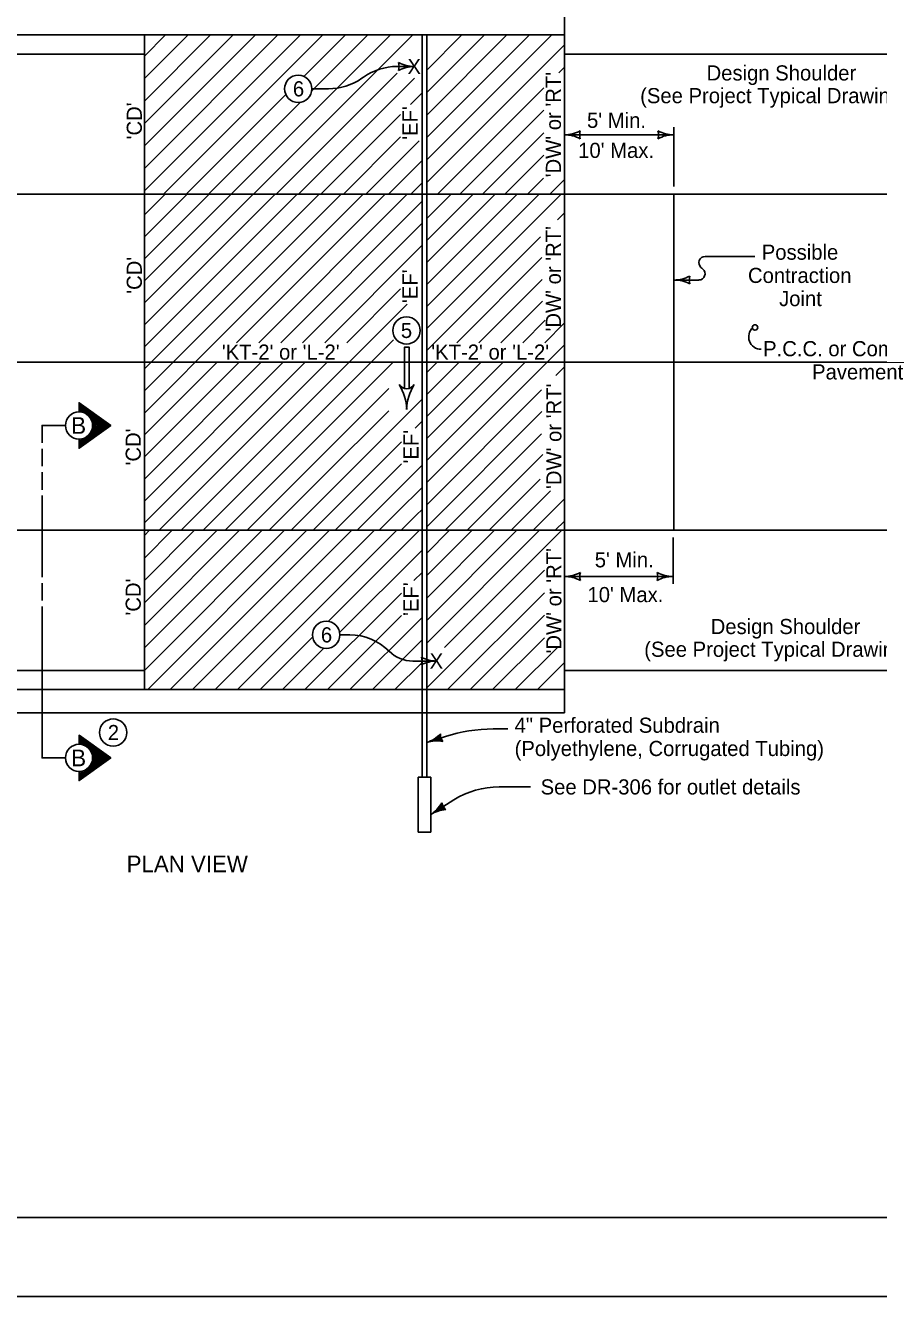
# Model space of a CAD drawing. Extents: x -2135039 to -2131695, y -2139150 to -2136566.
# Drawn here: x -2133962 to -2132834, y -2139150 to -2137471 of the extents above; entities that cross this region are included whole.
import ezdxf

# ---------------------------------------------------------------- set-up
doc = ezdxf.new("R2010")
doc.units = 0
for name, color, linetype in [('Default', 7, 'Continuous'), ('dsnDOTLogo', 7, 'Continuous'), ('Level 1', 7, 'Continuous'), ('Level 2', 7, 'Continuous'), ('Level 3', 7, 'Continuous')]:
    doc.layers.add(name, color=color, linetype=linetype)

msp = doc.modelspace()

# ---------------------------------------------------------------- linework, layer by layer
at = {"layer": 'Default'}
msp.add_line((-2134174.5, -2137483.5), (-2133249.3, -2137483.5), dxfattribs=at)
at = {"layer": 'dsnDOTLogo'}
msp.add_lwpolyline([(-2135038.9, -2139150.4), (-2131694.9, -2139150.4), (-2131694.9, -2136566.4), (-2135038.9, -2136566.4)], close=True, dxfattribs=at)
at = {"layer": 'Level 1'}
msp.add_lwpolyline([(-2134934.4, -2137035.9), (-2131799.4, -2137035.9), (-2131799.4, -2139045.9), (-2134934.4, -2139045.9)], close=True, dxfattribs=at)
at = {"layer": 'Level 2'}
for p, q in [((-2133249.3, -2137452.7), (-2133249.3, -2137509)), ((-2134174.5, -2137483.5), (-2133804.4, -2137483.5)), ((-2133804.4, -2137483.5), (-2134174.5, -2137483.5)), ((-2133804.4, -2137483.5), (-2133804.4, -2138138.1)), ((-2133804.4, -2137689.7), (-2133598.2, -2137483.5)), ((-2133804.4, -2137660), (-2133627.9, -2137483.5)), ((-2133804.4, -2137630.3), (-2133657.6, -2137483.5)), ((-2133804.4, -2137600.6), (-2133687.3, -2137483.5)), ((-2133804.4, -2137570.9), (-2133717, -2137483.5)), ((-2133804.4, -2137541.2), (-2133746.7, -2137483.5)), ((-2133804.4, -2137511.5), (-2133776.4, -2137483.5)), ((-2133779, -2137694), (-2133568.5, -2137483.5)), ((-2133689.9, -2137694), (-2133479.4, -2137483.5)), ((-2133660.2, -2137694), (-2133449.7, -2137483.5)), ((-2133593.7, -2137538.4), (-2133538.8, -2137483.5)), ((-2133583.4, -2137557.8), (-2133509.1, -2137483.5)), ((-2133437.4, -2137694), (-2133437.4, -2137483.5)), ((-2133431.3, -2137483.5), (-2133431.3, -2137694)), ((-2133431.3, -2137648.8), (-2133266, -2137483.5)), ((-2133431.3, -2137619.1), (-2133295.7, -2137483.5)), ((-2133431.3, -2137589.4), (-2133325.4, -2137483.5)), ((-2133431.3, -2137559.7), (-2133355.1, -2137483.5)), ((-2133431.3, -2137530), (-2133384.8, -2137483.5)), ((-2133249.3, -2137694), (-2133249.3, -2137483.5)), ((-2133804.4, -2137509), (-2134174.4, -2137509)), ((-2133804.4, -2137694), (-2133804.4, -2137509)), ((-2133804.4, -2137694), (-2133804.4, -2137509)), ((-2133437.4, -2137694), (-2133437.4, -2137509)), ((-2133431.3, -2137678.5), (-2133249.3, -2137496.6)), ((-2133431.3, -2137694), (-2133431.3, -2137509)), ((-2133249.3, -2137509), (-2132738.5, -2137509)), ((-2133249.3, -2137694), (-2133249.3, -2137509)), ((-2133447.7, -2137525.3), (-2133470.5, -2137525.3)), ((-2133256.6, -2137533.6), (-2133249.3, -2137526.3)), ((-2133630.5, -2137694), (-2133470.6, -2137534.1)), ((-2133600.8, -2137694), (-2133447.7, -2137540.9)), ((-2133514.7, -2137539.3), (-2133517, -2137540.9)), ((-2133749.3, -2137694), (-2133617.5, -2137562.2)), ((-2133561.2, -2137554.8), (-2133583.1, -2137554.8)), ((-2133452.6, -2137575.5), (-2133437.4, -2137560.3)), ((-2133417.1, -2137694), (-2133276.4, -2137553.4)), ((-2133719.6, -2137694), (-2133598.2, -2137572.6)), ((-2133571.1, -2137694), (-2133465.9, -2137588.7)), ((-2133387.4, -2137694), (-2133276.4, -2137583.1)), ((-2133357.7, -2137694), (-2133276.4, -2137612.8)), ((-2133541.4, -2137694), (-2133465.9, -2137618.4)), ((-2133511.7, -2137694), (-2133441.4, -2137623.7)), ((-2133328, -2137694), (-2133276.4, -2137642.5)), ((-2133482, -2137694), (-2133437.4, -2137649.4)), ((-2133249.3, -2137694), (-2133249.3, -2137657)), ((-2133452.3, -2137694), (-2133437.4, -2137679.1)), ((-2133298.3, -2137694), (-2133277, -2137672.7)), ((-2133268.6, -2137694), (-2133249.3, -2137674.8)), ((-2133249.3, -2137694), (-2134660.4, -2137694)), ((-2134174.4, -2137694), (-2133804.4, -2137694)), ((-2134174.4, -2137694), (-2133804.4, -2137694)), ((-2133804.4, -2137721.4), (-2133777, -2137694)), ((-2133804.4, -2137750.5), (-2133748, -2137694)), ((-2133804.4, -2137779.5), (-2133718.9, -2137694)), ((-2133804.4, -2137808.6), (-2133689.8, -2137694)), ((-2133804.4, -2137837.7), (-2133660.7, -2137694)), ((-2133804.4, -2137866.8), (-2133631.7, -2137694)), ((-2133804.4, -2137895.8), (-2133602.6, -2137694)), ((-2133804.4, -2137694), (-2133804.4, -2138138.1)), ((-2133599.8, -2137720.3), (-2133573.5, -2137694)), ((-2133582.4, -2137732), (-2133544.4, -2137694)), ((-2133556.4, -2137735.1), (-2133515.4, -2137694)), ((-2133508.1, -2137715.8), (-2133486.3, -2137694)), ((-2133465.7, -2137702.5), (-2133457.2, -2137694)), ((-2133437.4, -2138138.1), (-2133437.4, -2137694)), ((-2133431.3, -2138138.1), (-2133431.3, -2137694)), ((-2133431.3, -2137726.2), (-2133399.1, -2137694)), ((-2133431.3, -2137755.3), (-2133370, -2137694)), ((-2133431.3, -2137784.4), (-2133340.9, -2137694)), ((-2133431.3, -2137871.6), (-2133253.7, -2137694)), ((-2133431.3, -2137813.4), (-2133311.8, -2137694)), ((-2133431.3, -2137842.5), (-2133282.8, -2137694)), ((-2133249.3, -2137694), (-2132703.7, -2137694)), ((-2133104.9, -2137694), (-2133104.9, -2138138.1)), ((-2133653.4, -2137890.2), (-2133465.7, -2137702.5)), ((-2133624.3, -2137890.2), (-2133437.4, -2137703.3)), ((-2133804.4, -2137924.9), (-2133599.8, -2137720.3)), ((-2133682.5, -2137890.2), (-2133508.1, -2137715.8)), ((-2133258.5, -2137727.9), (-2133249.3, -2137718.7)), ((-2133804.4, -2137954), (-2133582.4, -2137732)), ((-2133690.9, -2137869.5), (-2133556.4, -2137735.1)), ((-2133595.3, -2137890.2), (-2133437.4, -2137732.4)), ((-2133556.4, -2137735.1), (-2133563.3, -2137741.9)), ((-2133566.2, -2137890.2), (-2133437.4, -2137761.5)), ((-2133431.3, -2137900.7), (-2133280.8, -2137750.2)), ((-2133391.7, -2137890.2), (-2133279.3, -2137777.7)), ((-2133066.4, -2137793), (-2133067.7, -2137791.8)), ((-2133804.9, -2137803.9), (-2133804.4, -2137803.5)), ((-2133362.7, -2137890.2), (-2133279, -2137806.5)), ((-2133537.1, -2137890.2), (-2133465.9, -2137819)), ((-2133755.9, -2138138.1), (-2133457.2, -2137839.4)), ((-2133333.6, -2137890.2), (-2133278.5, -2137835.2)), ((-2133304.5, -2137890.2), (-2133274.9, -2137860.6)), ((-2133275.4, -2137890.2), (-2133249.3, -2137864.1)), ((-2133804.4, -2137983.1), (-2133690.9, -2137869.5)), ((-2133726.8, -2138138.1), (-2133475.2, -2137886.4)), ((-2133431.3, -2138075.1), (-2133249.3, -2137893.2)), ((-2134174.5, -2137916), (-2132658.2, -2137916)), ((-2133804.4, -2138012.1), (-2133708.3, -2137916)), ((-2133804.4, -2138041.2), (-2133679.2, -2137916)), ((-2133804.4, -2138070.3), (-2133650.2, -2137916)), ((-2133804.4, -2138099.4), (-2133621.1, -2137916)), ((-2133730.1, -2138054.1), (-2133592, -2137916)), ((-2133715.6, -2138068.7), (-2133562.9, -2137916)), ((-2133697.8, -2138138.1), (-2133475.7, -2137916)), ((-2133431.3, -2138017), (-2133330.4, -2137916)), ((-2133431.3, -2137987.9), (-2133359.4, -2137916)), ((-2133431.3, -2138046), (-2133301.3, -2137916)), ((-2133431.3, -2137958.8), (-2133388.5, -2137916)), ((-2133431.3, -2137929.7), (-2133417.6, -2137916)), ((-2133260.8, -2137933.7), (-2133249.3, -2137922.2)), ((-2133668.7, -2138138.1), (-2133481.2, -2137950.6)), ((-2133552.3, -2138079.8), (-2133437.4, -2137965)), ((-2133460.9, -2137950.6), (-2133460.9, -2137950.6)), ((-2133454.5, -2137950.6), (-2133454.5, -2137950.6)), ((-2133431.3, -2138104.2), (-2133279.8, -2137952.7)), ((-2133568.7, -2138067.2), (-2133481.6, -2137980.1)), ((-2133431.3, -2138133.3), (-2133279.3, -2137981.3)), ((-2133446.5, -2138003.1), (-2133437.4, -2137994.1)), ((-2133407, -2138138.1), (-2133279.5, -2138010.6)), ((-2133523.8, -2138080.4), (-2133464.6, -2138021.2)), ((-2133501.3, -2138087), (-2133464.6, -2138050.3)), ((-2133377.9, -2138138.1), (-2133277.8, -2138038)), ((-2133804.4, -2138128.4), (-2133730.1, -2138054.1)), ((-2133639.6, -2138138.1), (-2133564.6, -2138063.1)), ((-2133484.8, -2138099.6), (-2133437.4, -2138052.2)), ((-2133785, -2138138.1), (-2133715.6, -2138068.7)), ((-2133610.5, -2138138.1), (-2133552.3, -2138079.8)), ((-2133581.5, -2138138.1), (-2133523.8, -2138080.4)), ((-2133552.4, -2138138.1), (-2133496.9, -2138082.6)), ((-2133469.3, -2138113.2), (-2133437.4, -2138081.3)), ((-2133348.9, -2138138.1), (-2133281.5, -2138070.7)), ((-2133523.3, -2138138.1), (-2133481.7, -2138096.5)), ((-2133319.8, -2138138.1), (-2133267.6, -2138085.9)), ((-2133290.7, -2138138.1), (-2133249.3, -2138096.7)), ((-2133494.2, -2138138.1), (-2133469.3, -2138113.2)), ((-2133465.2, -2138138.1), (-2133444.7, -2138117.6)), ((-2133261.6, -2138138.1), (-2133249.3, -2138125.8)), ((-2133804.4, -2138138.1), (-2134174.4, -2138138.1)), ((-2133804.4, -2138138.1), (-2134174.4, -2138138.1)), ((-2133804.4, -2138138.1), (-2133804.4, -2138323.1)), ((-2133804.4, -2138138.1), (-2133804.4, -2138323.1)), ((-2133804.4, -2138138.1), (-2133804.4, -2138348.6)), ((-2133804.4, -2138293.5), (-2133649, -2138138.1)), ((-2133804.4, -2138263.8), (-2133678.7, -2138138.1)), ((-2133804.4, -2138204.4), (-2133738.1, -2138138.1)), ((-2133804.4, -2138174.7), (-2133767.8, -2138138.1)), ((-2133804.4, -2138145), (-2133797.5, -2138138.1)), ((-2133804.4, -2138234.1), (-2133708.4, -2138138.1)), ((-2133804.4, -2138323.1), (-2133804.4, -2138138.1)), ((-2133804.3, -2138323.1), (-2133619.3, -2138138.1)), ((-2133800.1, -2138348.6), (-2133589.6, -2138138.1)), ((-2133770.4, -2138348.6), (-2133559.9, -2138138.1)), ((-2133740.7, -2138348.6), (-2133530.2, -2138138.1)), ((-2133711, -2138348.6), (-2133500.5, -2138138.1)), ((-2133681.3, -2138348.6), (-2133470.8, -2138138.1)), ((-2133561.4, -2138258.4), (-2133441.1, -2138138.1)), ((-2133437.4, -2138348.6), (-2133437.4, -2138138.1)), ((-2133431.3, -2138138.1), (-2133431.3, -2138348.6)), ((-2133431.3, -2138287), (-2133282.4, -2138138.1)), ((-2133431.3, -2138257.3), (-2133312.1, -2138138.1)), ((-2133431.3, -2138227.6), (-2133341.8, -2138138.1)), ((-2133431.3, -2138197.9), (-2133371.5, -2138138.1)), ((-2133431.3, -2138168.2), (-2133401.1, -2138138.1)), ((-2133431.3, -2138138.5), (-2133430.8, -2138138.1)), ((-2133407.7, -2138293.1), (-2133252.7, -2138138.1)), ((-2133249.3, -2138138.1), (-2133249.3, -2138175.1)), ((-2133249.3, -2138138.1), (-2132703.7, -2138138.1)), ((-2133249.3, -2138323.1), (-2133249.3, -2138138.1)), ((-2133249.3, -2138348.6), (-2133249.3, -2138138.1)), ((-2133546.5, -2138273.1), (-2133437.4, -2138164.1)), ((-2133448.3, -2138204.6), (-2133437.4, -2138193.8)), ((-2133431.3, -2138346.4), (-2133275.8, -2138190.9)), ((-2133592.2, -2138348.6), (-2133464.6, -2138221)), ((-2133403.7, -2138348.6), (-2133275.8, -2138220.6)), ((-2133562.5, -2138348.6), (-2133464.6, -2138250.7)), ((-2133374, -2138348.6), (-2133275.8, -2138250.3)), ((-2133532.8, -2138348.6), (-2133437.4, -2138253.2)), ((-2133651.6, -2138348.6), (-2133582, -2138279)), ((-2133503.1, -2138348.6), (-2133437.4, -2138282.9)), ((-2133344.3, -2138348.6), (-2133275.8, -2138280)), ((-2133621.9, -2138348.6), (-2133567.3, -2138293.9)), ((-2133314.6, -2138348.6), (-2133257.4, -2138291.4)), ((-2133473.4, -2138348.6), (-2133437.4, -2138312.6)), ((-2133284.9, -2138348.6), (-2133249.3, -2138312.9)), ((-2134174.4, -2138323.1), (-2133804.4, -2138323.1)), ((-2133249.3, -2138323.1), (-2132738.5, -2138323.1)), ((-2133249.3, -2138379.4), (-2133249.3, -2138323.1)), ((-2134174.5, -2138348.6), (-2133249.3, -2138348.6)), ((-2133437.4, -2138348.6), (-2133437.4, -2138464.3)), ((-2133431.3, -2138348.6), (-2133431.3, -2138464.3)), ((-2134137.5, -2138379.4), (-2133249.3, -2138379.4)), ((-2133406.7, -2138410.4), (-2133431.3, -2138418.3)), ((-2133431.3, -2138418.3), (-2133412.5, -2138412.2)), ((-2133442.6, -2138464.3), (-2133426.1, -2138464.3)), ((-2133442.6, -2138464.3), (-2133442.6, -2138536.7)), ((-2133426.1, -2138464.3), (-2133426.1, -2138536.7)), ((-2133426.1, -2138513.5), (-2133409.4, -2138503)), ((-2133442.6, -2138536.7), (-2133426.1, -2138536.7))]:
    msp.add_line(p, q, dxfattribs=at)
for points in [[(-2134174.4, -2137501.3), (-2134174.5, -2137501.3), (-2134174.5, -2137483.5), (-2133804.4, -2137483.5), (-2133804.4, -2137509), (-2134174.4, -2137509)], [(-2134174.4, -2138330.8), (-2134174.4, -2138323.1), (-2133804.4, -2138323.1), (-2133804.4, -2138348.6), (-2134174.5, -2138348.6), (-2134174.5, -2138330.8)]]:
    msp.add_lwpolyline(points, close=True, dxfattribs=at)
for points in [[(-2133437.4, -2137694), (-2133437.4, -2137694)], [(-2133431.3, -2137694), (-2133431.3, -2137694)], [(-2133454.5, -2137950.6), (-2133454.5, -2137896.2), (-2133460.9, -2137896.2), (-2133460.9, -2137950.6)], [(-2133890.8, -2137981.6), (-2133890.8, -2137969.6), (-2133848.8, -2137999.6), (-2133890.8, -2138029.6), (-2133890.8, -2138017.6)], [(-2133889.6, -2138018.8), (-2133889.7, -2138027.4), (-2133851, -2137999.6), (-2133889.8, -2137971.5), (-2133889.5, -2137980.7), (-2133887.9, -2137981.2), (-2133888.5, -2137974.5), (-2133853.6, -2137999.6), (-2133888.5, -2138025), (-2133888.1, -2138018.6), (-2133886.9, -2138018.3), (-2133887, -2138022.6), (-2133855.9, -2137999.5), (-2133887.1, -2137977.6), (-2133886.4, -2137981.3), (-2133885.1, -2137981.6), (-2133885.2, -2137980.4), (-2133858.5, -2137999.8), (-2133885.7, -2138020.3), (-2133884.3, -2138018), (-2133860.9, -2138000), (-2133875.3, -2137988.6), (-2133874.4, -2137990.7), (-2133863.3, -2138000.1), (-2133874, -2138008.3), (-2133873, -2138006.1), (-2133865.6, -2138000.4), (-2133873, -2137993.9), (-2133872.3, -2137996.8), (-2133867.5, -2138000.5), (-2133872.4, -2138004.3), (-2133872.1, -2138002.3), (-2133869.3, -2138000.6), (-2133872, -2137998.9), (-2133871.9, -2138000.6), (-2133870.9, -2138000.6)], [(-2133437.4, -2138138.1), (-2133437.4, -2138138.1)], [(-2133890.8, -2138420.8), (-2133890.8, -2138408.8), (-2133848.8, -2138438.8), (-2133890.8, -2138468.8), (-2133890.8, -2138456.8)], [(-2133889.6, -2138458), (-2133889.7, -2138466.7), (-2133851, -2138438.8), (-2133889.8, -2138410.7), (-2133889.5, -2138419.9), (-2133887.9, -2138420.4), (-2133888.5, -2138413.7), (-2133853.6, -2138438.8), (-2133888.5, -2138464.2), (-2133888.1, -2138457.8), (-2133886.9, -2138457.5), (-2133887, -2138461.8), (-2133855.9, -2138438.7), (-2133887.1, -2138416.8), (-2133886.4, -2138420.5), (-2133885.1, -2138420.8), (-2133885.2, -2138419.6), (-2133858.5, -2138439), (-2133885.7, -2138459.5), (-2133884.3, -2138457.2), (-2133860.9, -2138439.2), (-2133875.3, -2138427.8), (-2133874.4, -2138429.9), (-2133863.3, -2138439.3), (-2133874, -2138447.5), (-2133873, -2138445.3), (-2133865.6, -2138439.6), (-2133873, -2138433.2), (-2133872.3, -2138436), (-2133867.5, -2138439.7), (-2133872.4, -2138443.5), (-2133872.1, -2138441.5), (-2133869.3, -2138439.8), (-2133872, -2138438.1), (-2133871.9, -2138439.9), (-2133870.9, -2138439.8)], [(-2133411.7, -2138415.8), (-2133413.6, -2138412.6), (-2133414, -2138408.8), (-2133417.5, -2138412.2), (-2133423.7, -2138415.8), (-2133416, -2138415.2), (-2133412.4, -2138415.6), (-2133414.2, -2138412.8), (-2133414.6, -2138410.4), (-2133417, -2138412.6), (-2133420.4, -2138414.8), (-2133416.1, -2138414.6), (-2133413.8, -2138414.7), (-2133415.1, -2138411.8), (-2133417.5, -2138413.8), (-2133415.1, -2138413.8), (-2133415.4, -2138412.8), (-2133416.3, -2138413.4)], [(-2133407.8, -2138506.3), (-2133410.4, -2138503.6), (-2133411.7, -2138500.1), (-2133414.3, -2138504.2), (-2133419.4, -2138509.3), (-2133412.1, -2138506.7), (-2133408.5, -2138506.3), (-2133410.9, -2138504), (-2133411.9, -2138501.8), (-2133413.7, -2138504.5), (-2133416.4, -2138507.4), (-2133412.3, -2138506.2), (-2133410.1, -2138505.7), (-2133412.1, -2138503.2), (-2133413.9, -2138505.8), (-2133411.6, -2138505.2), (-2133412.1, -2138504.3), (-2133412.8, -2138505.1)]]:
    msp.add_lwpolyline(points, dxfattribs=at)
for centre, radius in [((-2133601.1, -2137554.8), 18), ((-2133458.1, -2137874), 18), ((-2132997.6, -2137870.1), 3.6), ((-2133890.8, -2137999.6), 18), ((-2133564.2, -2138276.2), 18), ((-2133845.7, -2138405.3), 18), ((-2133890.8, -2138438.8), 18)]:
    msp.add_circle(centre, radius, dxfattribs=at)
for centre, radius, start, end in [((-2133470.5, -2137602.4), 77.1, 90, 124.9993), ((-2133484.9, -2137525.3), 17.1, 342.2666, 17.7334), ((-2133447.7, -2137480.9), 44.4, 241.9275, 270), ((-2133484.9, -2137525.3), 17.1, 342.2666, 17.7334), ((-2133447.7, -2137480.9), 44.4, 241.9275, 270), ((-2133447.7, -2137569.7), 44.4, 90, 118.0725), ((-2133447.7, -2137569.7), 44.4, 90, 118.0725), ((-2133561.2, -2137477.7), 77.1, 270, 304.9999), ((-2133249.3, -2137571.2), 44.4, 270, 298.0725), ((-2133212.1, -2137615.5), 17.1, 162.2666, 197.7334), ((-2133142.1, -2137615.5), 17.1, 342.2666, 17.7334), ((-2133104.9, -2137571.2), 44.4, 241.9275, 270), ((-2133249.3, -2137659.9), 44.4, 61.9275, 90), ((-2133104.9, -2137659.9), 44.4, 90, 118.0725), ((-2133104.6, -2137763), 44.4, 270, 298.0725), ((-2133104.6, -2137851.7), 44.4, 61.9275, 90), ((-2133067.4, -2137807.4), 17.1, 162.2666, 197.7334), ((-2133457.8, -2137939.4), 11.6, 211.7147, 328.2853), ((-2133524.1, -2137980.4), 66.3, 1.6842, 31.7143), ((-2133457.8, -2137939.4), 11.6, 211.7169, 254.5904), ((-2133524.1, -2137980.4), 66.3, 1.6842, 31.7139), ((-2133391.6, -2137980.4), 66.3, 148.2857, 178.3158), ((-2133391.6, -2137980.4), 66.3, 148.2862, 178.3158), ((-2133457.8, -2137939.4), 11.6, 286.4809, 328.2829), ((-2133249.3, -2138154.4), 44.6, 270, 298.0725), ((-2133249.3, -2138154.4), 44.6, 270, 298.0725), ((-2133249.3, -2138243.6), 44.6, 61.9275, 90), ((-2133249.3, -2138243.6), 44.6, 61.9275, 90), ((-2133211.9, -2138199), 17.2, 162.2666, 197.7334), ((-2133211.9, -2138199), 17.2, 162.2666, 197.7334), ((-2133143.2, -2138199), 17.2, 342.2666, 17.7334), ((-2133105.8, -2138154.4), 44.6, 241.9275, 270), ((-2133105.8, -2138243.6), 44.6, 90, 118.0725), ((-2133453.8, -2138310.8), 16.3, 342.2666, 17.7333), ((-2133418.4, -2138268.5), 42.3, 241.9275, 270), ((-2133418.4, -2138353.1), 42.3, 90, 118.0725), ((-2133444.7, -2138376.7), 43.7, 287.8585, 315.9309), ((-2133417.9, -2138459.9), 43.7, 79.786, 107.8585), ((-2133396.4, -2138407.1), 16.9, 180.1251, 215.5918), ((-2133449.3, -2138476.5), 43.7, 302.0841, 330.1566), ((-2133395.1, -2138494), 16.9, 194.3508, 229.8175), ((-2133402.9, -2138550.5), 43.7, 94.0116, 122.0841)]:
    msp.add_arc(centre, radius, start, end, dxfattribs=at)
at = {"layer": 'Level 3'}
for p, q in [((-2133249.3, -2137646.7), (-2133249.3, -2137605.3)), ((-2133104.9, -2137683.7), (-2133104.9, -2137605.3)), ((-2133104.9, -2137615.5), (-2133249.3, -2137615.5)), ((-2133249.3, -2137694), (-2133249.3, -2138138.1)), ((-2133063.5, -2137776.3), (-2132997.9, -2137776.3)), ((-2133067.7, -2137791.8), (-2133068.9, -2137790.7)), ((-2133104.6, -2137807.4), (-2133071.8, -2137807.4)), ((-2133444.7, -2138117.6), (-2133437.4, -2138110.4)), ((-2134613.7, -2138138.1), (-2133249.3, -2138138.1)), ((-2133105.8, -2138147.7), (-2133105.8, -2138208.6)), ((-2133249.3, -2138184.7), (-2133249.3, -2138208.6)), ((-2133249.3, -2138199), (-2133105.8, -2138199)), ((-2133939.6, -2138238.6), (-2133939.6, -2138438.8)), ((-2133533, -2138276.2), (-2133546.2, -2138276.2)), ((-2133418.4, -2138310.8), (-2133449.7, -2138310.8)), ((-2133324, -2138400.5), (-2133343.6, -2138400.5)), ((-2133294, -2138477.1), (-2133335.5, -2138477.1)), ((-2133395.5, -2138494.3), (-2133426.1, -2138513.5))]:
    msp.add_line(p, q, dxfattribs=at)
for points in [[(-2133908.8, -2137999.6), (-2133939.6, -2137999.6), (-2133939.6, -2138022.7)], [(-2133939.6, -2138030.4), (-2133939.6, -2138053.5)], [(-2133939.6, -2138061.3), (-2133939.6, -2138084.4)], [(-2133939.6, -2138092.1), (-2133939.6, -2138200)], [(-2133939.6, -2138207.7), (-2133939.6, -2138230.9)], [(-2133939.6, -2138427.4), (-2133939.6, -2138438.8), (-2133908.8, -2138438.8)]]:
    msp.add_lwpolyline(points, dxfattribs=at)
for centre, radius, start, end in [((-2133063.5, -2137784.5), 8.22, 90, 228.6908), ((-2133071.8, -2137799.1), 8.22, 270, 48.691), ((-2132989.5, -2137882.5), 16.4, 131.3092, 270), ((-2133533, -2138349.6), 73.4, 45, 90), ((-2133449.7, -2138266.7), 44.1, 225, 270), ((-2133343.6, -2138606.1), 205.6, 90, 107.8594), ((-2133335.5, -2138590.1), 113.1, 90, 122.0832)]:
    msp.add_arc(centre, radius, start, end, dxfattribs=at)

# ---------------------------------------------------------------- texts
for s, height, p in [('X', 20, (-2133456.8, -2137535.3)), ('Design Shoulder', 20, (-2133061.5, -2137543.8)), ('6', 20, (-2133608.2, -2137564.8)), ('(See Project Typical Drawings)', 20, (-2133149.3, -2137573.8)), ("5' Min.", 20, (-2133219.5, -2137606.4)), ("10' Max.", 20, (-2133231.2, -2137646.1)), ('Possible', 20, (-2132988.6, -2137780.6)), ('Contraction', 20, (-2133006.8, -2137811.3)), ('Joint', 20, (-2132965.7, -2137841.9)), ('5', 20, (-2133465.5, -2137884)), ("'KT-2' or 'L-2'", 20, (-2133702.1, -2137912.6)), ("'KT-2' or 'L-2'", 20, (-2133425.3, -2137912.6)), ('P.C.C. or Composite', 20, (-2132986.8, -2137908.1)), ('Pavement', 20, (-2132922.1, -2137938.8)), ('B', 22, (-2133901.1, -2138010.6)), ("5' Min.", 20, (-2133209.3, -2138187)), ("10' Max.", 20, (-2133218.9, -2138233)), ('6', 20, (-2133571.2, -2138286.2)), ('Design Shoulder', 20, (-2133056.1, -2138275.2)), ('(See Project Typical Drawings)', 20, (-2133143.9, -2138305.2)), ('X', 20, (-2133427.5, -2138320.8)), ('4" Perforated Subdrain ', 20, (-2133315.2, -2138405.6)), ('2', 20, (-2133852.8, -2138415.3)), ('(Polyethylene, Corrugated Tubing)', 20, (-2133315.2, -2138436.3)), ('B', 22, (-2133901.1, -2138449.8)), ('See DR-306 for outlet details', 20, (-2133280.8, -2138487.1)), ('PLAN VIEW', 22, (-2133827.9, -2138589.8))]:
    msp.add_text(s, height=height, dxfattribs=at).set_placement(p)
for s, p in [("'DW' or 'RT'", (-2133254, -2137671.7)), ("'CD'", (-2133807.8, -2137621.6)), ("'EF'", (-2133443.5, -2137622.1)), ("'DW' or 'RT'", (-2133254, -2137875.4)), ("'CD'", (-2133807.8, -2137825.6)), ("'EF'", (-2133443.5, -2137837.8)), ("'DW' or 'RT'", (-2133253.4, -2138083.5)), ("'CD'", (-2133809.2, -2138052.4)), ("'EF'", (-2133442.2, -2138049.8)), ("'DW' or 'RT'", (-2133253.4, -2138300.8)), ("'CD'", (-2133809.2, -2138250.7)), ("'EF'", (-2133442.2, -2138251.2))]:
    msp.add_text(s, height=20, rotation=90, dxfattribs=at).set_placement(p)

doc.saveas('drawing.dxf')
